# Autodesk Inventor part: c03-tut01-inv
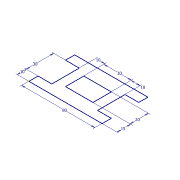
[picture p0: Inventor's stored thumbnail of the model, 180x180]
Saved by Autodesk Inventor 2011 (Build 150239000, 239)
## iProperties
Created: 2010-01
Part Number: c03-tut01-inv
Document SubType Name: Modeling
Designer: CADSoft
Density: 1 g/cm^3
Author: CADSoft
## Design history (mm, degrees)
sketch "Sketch1"
  geometry: L1 (80, 0)-(0, 0); L2 (0, 0)-(0, 10); L3 (0, 10)-(15, 10); L4 (15, 10)-(15, 40); L5 (15, 40)-(0, 40); L6 (0, 40)-(0, 50); L7 (0, 50)-(80, 50); L8 (80, 50)-(80, 40); L9 (80, 40)-(65, 40); L10 (65, 40)-(65, 10); L11 (65, 10)-(80, 10); L12 (80, 10)-(80, 0); L13 (25, 35)-(55, 35); L14 (55, 35)-(55, 15); L15 (55, 15)-(25, 15); L16 (25, 15)-(25, 35); 2 further points
  constraints: 32 end point, 9 equal length, 7 horizontal, 6 vertical, 2 coincident, 1 other
  dimensions: "d1" = 80 distance of L1.start L1.end; "d2" = 10 distance of L1.end L2.end; "d3" = 30 distance of L3.end L4.end; "d4" = 20 distance of L13.end L14.end; "d5" = 30 distance of L13.start L13.end; "d6" = 10 distance between parallel lines of L16 L4; "d7" = 10 distance between parallel lines of L10 L14; "d8" = 15 distance between parallel lines of L15 L1
